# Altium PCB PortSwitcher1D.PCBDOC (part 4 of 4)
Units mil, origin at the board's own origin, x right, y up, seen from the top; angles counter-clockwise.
Board outline 6005.03 x 6005.03 mil, 4 copper layers (Top Layer, InternalPlane1, InternalPlane2, Bottom Layer); 153 components, 325 nets, 1175 pads, 173 vias.
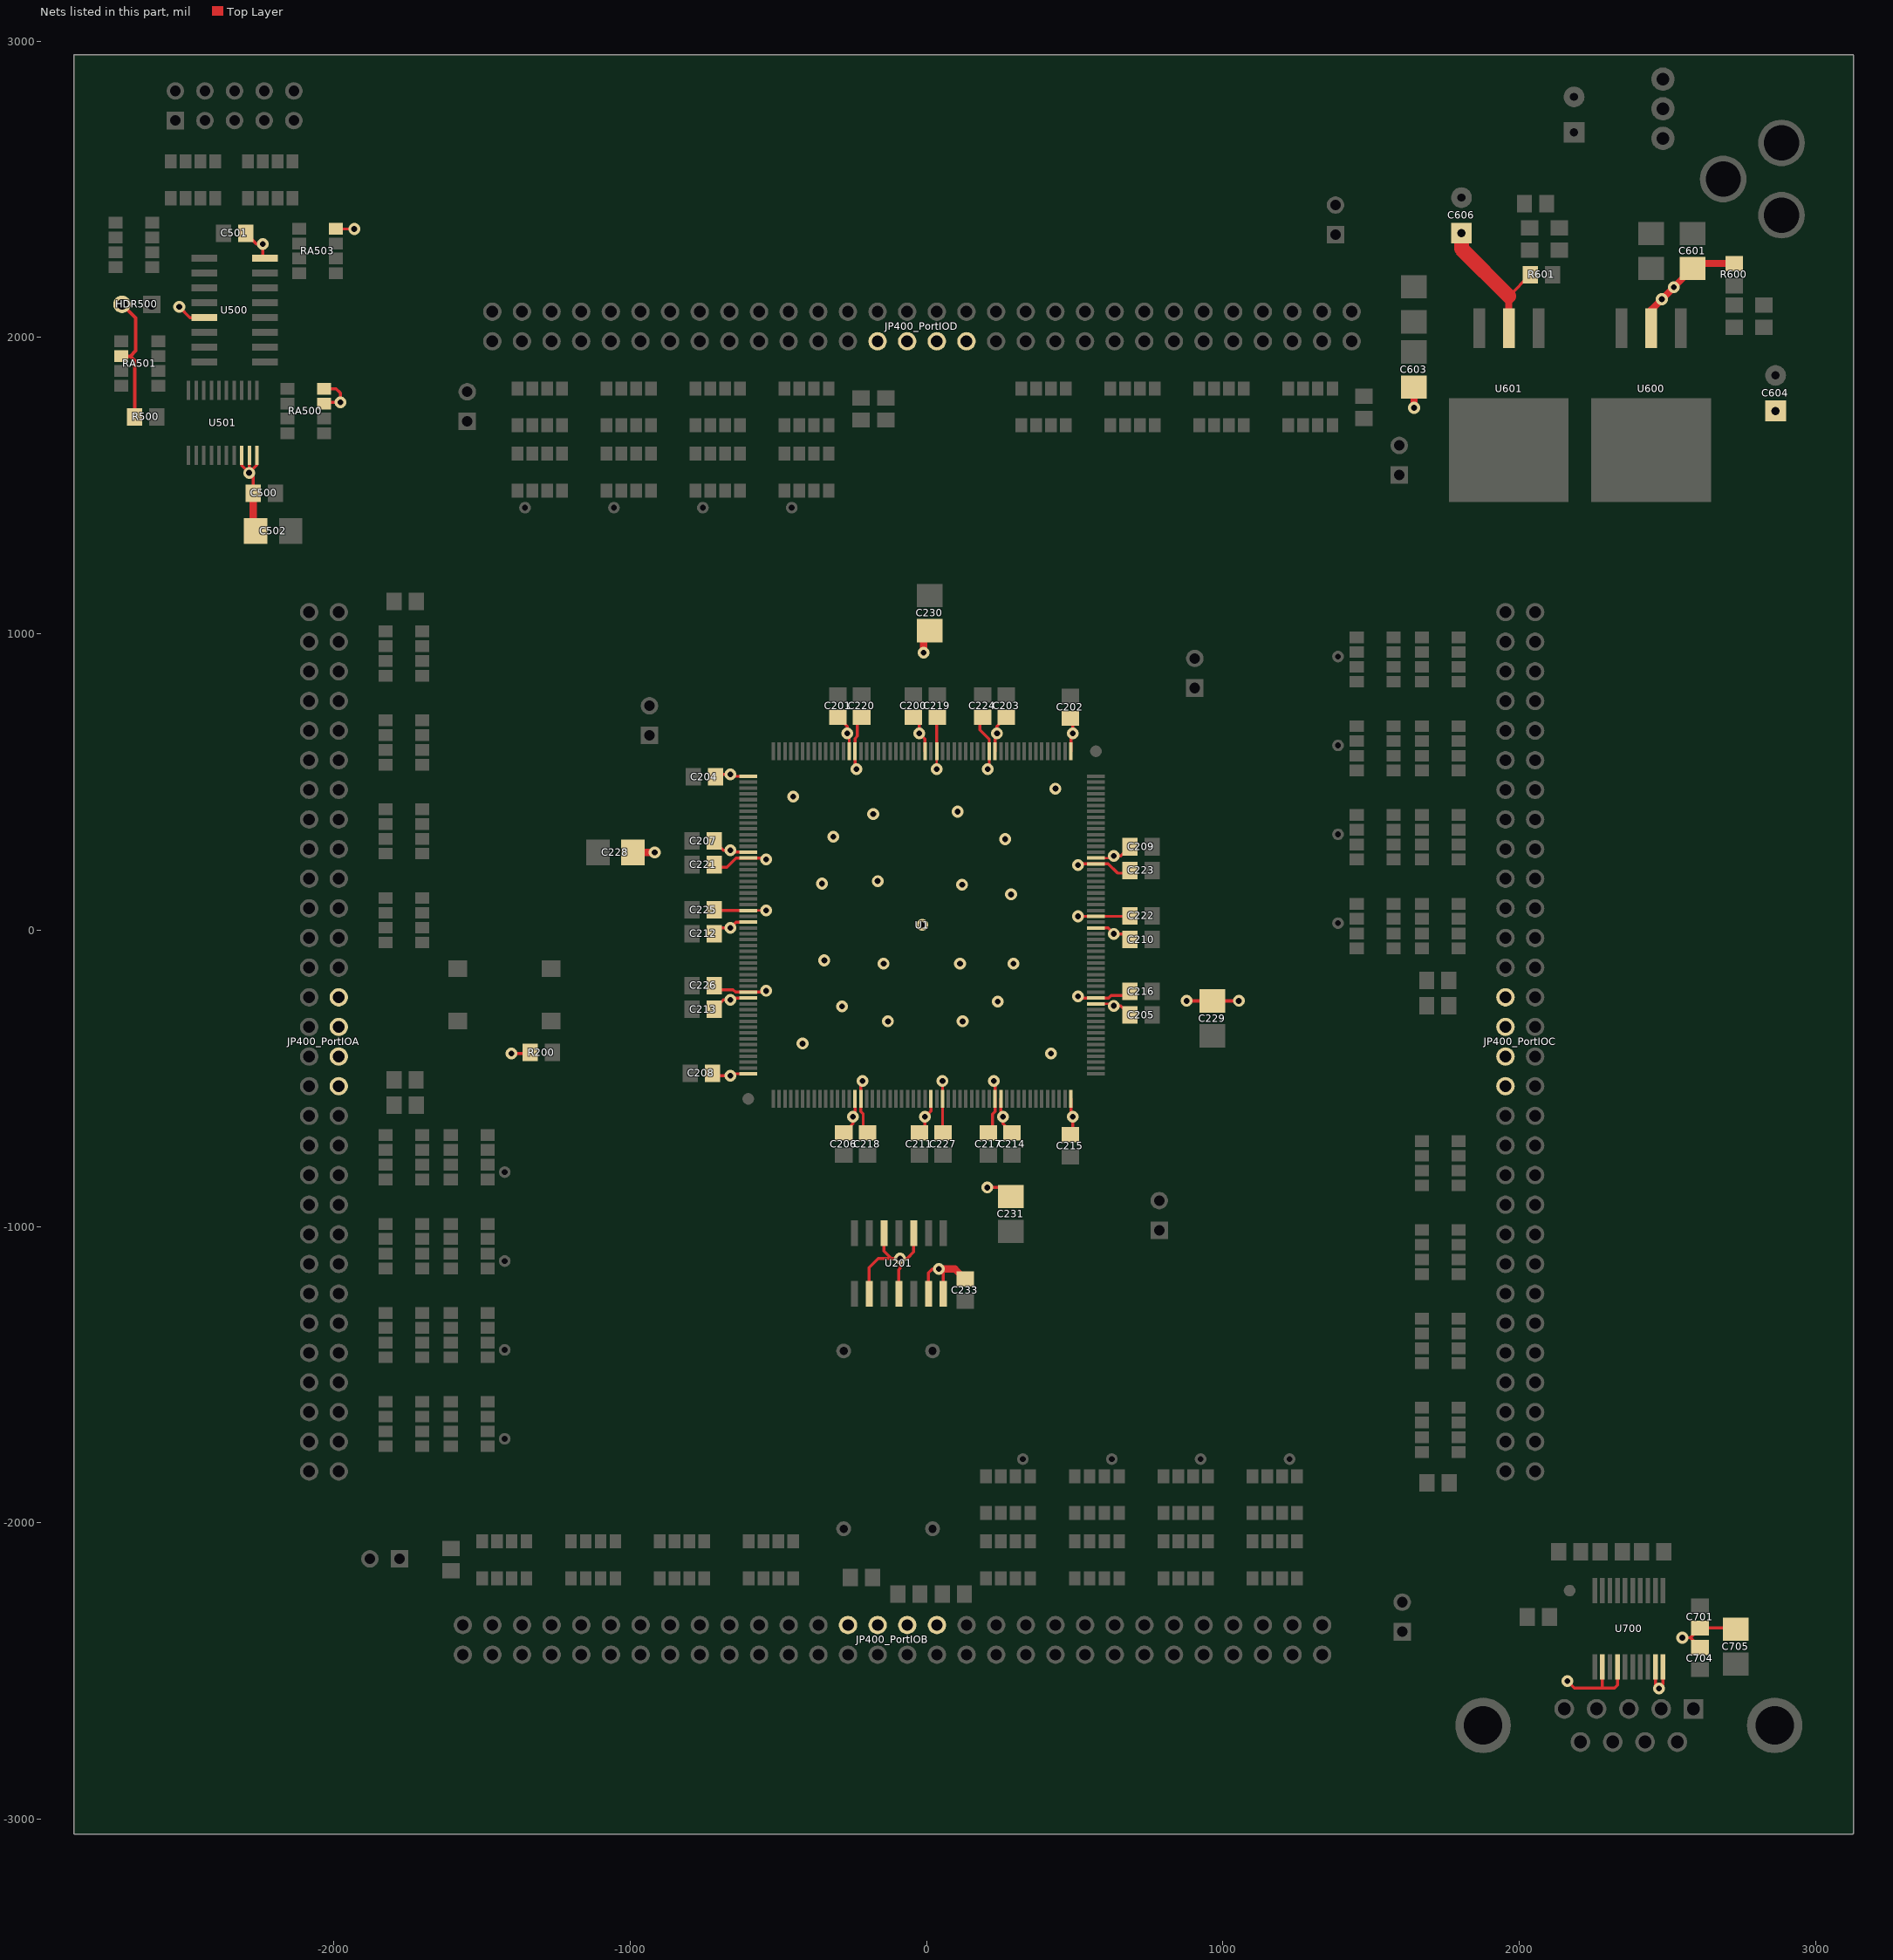
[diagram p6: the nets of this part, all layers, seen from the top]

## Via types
v1: diameter 40, hole 19.68, Top Layer to Bottom Layer, 173 vias

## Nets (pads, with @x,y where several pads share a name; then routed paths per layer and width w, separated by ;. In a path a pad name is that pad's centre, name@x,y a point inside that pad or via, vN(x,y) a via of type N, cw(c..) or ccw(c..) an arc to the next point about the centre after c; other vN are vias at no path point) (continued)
VCCINT: C216.1 C217.1 C218.1 C219.1 C220.1 C221.1 C222.2 C223.2 C224.2 C225.2 C226.2 C227.2 C230.1 C231.1 C603.1 C606.1 R601.2 U1.14 U1.28 U1.37 U1.67 U1.76 U1.90 U1.119 U1.128 U1.142 U1.172 U1.186 U1.195 U601.2 | length 4663.1
  Top Layer w8: U1.128@-601.88,66.5 v1(-541.37,66.5) U1.128@-601.88,66.5 ; v1(33.95,543.45) U1.76@33.95,603.91 v1(33.95,543.45) ; U1.186@53.63,-569.32 v1(53.63,-508.81) U1.186@53.63,-569.32 ; v1(510.84,46.82) U1.28@571.35,46.82 v1(510.84,46.82)
  Top Layer w10: C226.2@-717.86,-172.71 C226.2@-717.86,-177.12 ; C221.1@-712.86,212.29 -674.55,212.29 -643.17,243.67 ; C220.1@-205.26,719.89 C220.1@-209.67,719.89 ; C218.1@-185.58,-685.31 C218.1@-189.99,-685.31 ; C224.2@179.74,714.89 179.74,676.58 211.11,645.2 ; C217.1@194.42,-685.31 198.83,-685.31 C217.1@204.13,-680.01 ; v1(204.22,-868.54) 254.62,-868.53 C231.1@284.74,-898.65 ; C223.2@682.33,192.61 644.02,192.61 612.64,223.99 ; C216.1@687.33,-192.39 C216.1@687.33,-196.8 ; 1964.74,2139.69 R601.2@2037.33,2212.29 ; C226.2@-717.86,-177.12 C226.2@-712.57,-182.41 ; C226.2@-717.86,-177.12 C226.2@-712.57,-182.41 ; C226.2@-712.57,-182.41 C226.2@-693.89,-201.09 ; C226.2@-712.57,-182.41 C226.2@-693.89,-201.09 ; C225.2@-710.36,74.79 C225.2@-702.07,66.5 ; C225.2@-710.36,74.79 -717.86,82.29 C225.2@-710.36,74.79 ; C225.2@-710.36,74.79 C225.2@-702.07,66.5 ; C225.2@-702.07,66.5 U1.128@-601.88,66.5 C225.2@-702.07,66.5 ; C226.2@-693.89,-201.09 -652.88,-201.09 -644.89,-209.09 ; -644.89,-209.09 U1.142@-601.88,-209.09 ; -644.89,-209.09 U1.142@-601.88,-209.09 ; -643.17,243.67 U1.119@-601.88,243.67 ; -643.17,243.67 U1.119@-601.88,243.67 ; U1.142@-601.88,-209.09 v1@-545.8,-209.09 ; U1.142@-601.88,-209.09 v1@-545.8,-209.09 ; U1.119@-601.88,243.67 v1@-546.61,243.67 ; U1.119@-601.88,243.67 v1@-546.61,243.67 ; v1@-546.61,243.67 v1(-541.39,238.45) v1@-546.61,243.67 ; v1@-545.8,-209.09 v1(-541.39,-204.68) v1@-545.8,-209.09 ; v1@-241.64,547.83 v1(-237.23,543.42) v1@-241.64,547.83 ; v1@-241.64,547.83 U1.90@-241.64,603.91 ; v1@-241.64,547.83 U1.90@-241.64,603.91 ; U1.90@-241.64,603.91 -241.64,646.92 ; U1.90@-241.64,603.91 -241.64,646.92 ; -241.64,646.92 -233.65,654.91 C220.1@-233.65,695.91 ; C220.1@-233.65,695.91 C220.1@-214.97,714.59 ; C220.1@-233.65,695.91 C220.1@-214.97,714.6 ; -221.96,-612.34 -213.96,-620.33 -213.96,-661.33 -199.58,-675.72 C218.1@-195.28,-680.01 ; -221.96,-612.34 U1.172@-221.96,-569.32 ; -221.96,-612.34 U1.172@-221.96,-569.32 ; U1.172@-221.96,-569.32 v1@-221.96,-514.05 ; U1.172@-221.96,-569.32 v1@-221.96,-514.05 ; v1@-221.96,-514.05 v1(-216.74,-508.83) v1@-221.96,-514.05 ; C220.1@-214.97,714.59 C220.1@-209.67,719.89 ; C220.1@-214.97,714.6 C220.1@-209.67,719.89 ; C218.1@-195.28,-680.01 C218.1@-189.99,-685.31 ; C218.1@-195.28,-680.01 C218.1@-189.99,-685.31 ; C219.1@33.95,704.1 U1.76@33.95,603.91 C219.1@33.95,704.1 ; C219.1@33.95,704.1 C219.1@42.24,712.39 ; C219.1@33.95,704.1 C219.1@42.24,712.39 ; C219.1@42.24,712.39 49.74,719.89 C219.1@42.24,712.39 ; C227.2@53.63,-669.52 55.42,-671.31 C227.2@61.92,-677.81 ; C227.2@53.63,-669.52 U1.186@53.63,-569.32 C227.2@53.63,-669.52 ; C227.2@53.63,-669.52 C227.2@61.92,-677.81 ; C227.2@61.92,-677.81 69.42,-685.31 C227.2@61.92,-677.81 ; C217.1@204.13,-680.01 208.42,-675.72 C217.1@222.81,-661.33 ; C217.1@204.13,-680.01 C217.1@222.81,-661.33 ; v1@211.11,548.64 v1(205.89,543.42) v1@211.11,548.64 ; v1@211.11,548.64 U1.67@211.11,603.91 ; v1@211.11,548.64 U1.67@211.11,603.91 ; U1.67@211.11,603.91 211.11,645.2 ; U1.67@211.11,603.91 211.11,645.2 ; C217.1@222.81,-661.33 222.81,-620.33 230.8,-612.34 ; 230.8,-612.34 U1.195@230.8,-569.32 ; 230.8,-612.34 U1.195@230.8,-569.32 ; U1.195@230.8,-569.32 v1@230.8,-513.24 ; U1.195@230.8,-569.32 v1@230.8,-513.24 ; v1@230.8,-513.24 v1(226.39,-508.83) v1@230.8,-513.24 ; v1@515.27,223.98 v1(510.86,219.57) v1@515.27,223.98 ; v1@515.27,223.98 U1.37@571.35,223.98 ; v1@515.27,223.98 U1.37@571.35,223.98 ; v1@516.08,-228.77 v1(510.86,-223.55) v1@516.08,-228.77 ; v1@516.08,-228.77 U1.14@571.35,-228.77 ; v1@516.08,-228.77 U1.14@571.35,-228.77 ; U1.14@571.35,-228.77 614.36,-228.77 ; U1.14@571.35,-228.77 614.36,-228.77 ; U1.37@571.35,223.98 612.64,223.99 ; U1.37@571.35,223.98 612.64,223.99 ; 614.36,-228.77 622.36,-220.78 C216.1@663.36,-220.78 ; C216.1@663.36,-220.78 C216.1@682.04,-202.1 ; C216.1@663.36,-220.78 C216.1@682.04,-202.1 ; C216.1@682.04,-202.1 C216.1@687.33,-196.8 ; C216.1@682.04,-202.1 C216.1@687.33,-196.8 ; U1.28@571.35,46.82 671.55,46.82 U1.28@571.35,46.82
  Top Layer w24: v1(-10.34,936.35) -10.34,1013.16 C230.1@-10.26,1013.24 ; v1(1644.74,1762.91) C603.1@1644.74,1833.24 ; U601.2@1964.74,2032.29 1964.74,2139.69
  Top Layer w50: C606.1@1804.74,2352.29 1804.74,2299.69 1964.74,2139.69
  other v1: 419.74,-415.67 -418.7,-382.71 -130.39,-307.71 121.51,-307.71 -285.26,-257.24 239.74,-240.52 -145.15,-112.71 112.66,-112.71 292.73,-112.71 -345.26,-101.77 -15.26,18.28 284.74,120.61 119.74,153.08 -352.78,157.29 -165.26,165.88 265.18,307.29 -315.26,315.44 -180.26,392.2 104.74,400.07 -450.26,451.24 434.74,477.8
VCCO: C200.1 C201.1 C202.1 C203.1 C204.1 C205.1 C206.1 C207.1 C208.2 C209.2 C210.2 C211.2 C212.2 C213.2 C214.2 C215.2 C228.1 C229.1 C233.1 C500.1 C501.1 C502.1 C601.1 C604.1 C701.1 C704.1 C705.1 HDR500.2 JP400_PortIOA.28 JP400_PortIOA.30 JP400_PortIOA.32 JP400_PortIOA.34 JP400_PortIOB.28 JP400_PortIOB.30 JP400_PortIOB.32 JP400_PortIOB.34 JP400_PortIOC.28 JP400_PortIOC.30 JP400_PortIOC.32 JP400_PortIOC.34 JP400_PortIOD.28 JP400_PortIOD.30 JP400_PortIOD.32 JP400_PortIOD.34 pad.0 R200.2 R500.1 R600.2 RA500.7 RA500.8 RA501.6 RA503.8 U1.13 U1.26 U1.38 U1.53 U1.66 U1.78 U1.91 U1.105 U1.118 U1.130 U1.143 U1.156 U1.171 U1.184 U1.196 U1.208 U201.3 U201.5 U201.9 U201.11 U201.13 U201.14 U500.5 U500.16 U501.18 U501.19 U501.20 U600.2 U700.12 U700.14 U700.19 U700.20 | length 7901
  Top Layer w8: v1@-254.28,-632.31 -250.07,-628.1 v1@-244.28,-622.31 ; -241.64,-604.68 U1.171@-241.64,-569.32 ; v1@253.12,-622.31 v1@258.91,-628.1 ; v1@-660.65,-237.19 -661.17,-237.71 -662.39,-238.93 -664.22,-240.76 -664.87,-241.41 v1@-660.65,-237.19 ; v1@-660.65,-237.19 -654.87,-231.41 v1@-660.65,-237.19 ; v1@-269.75,662.68 -263.97,656.9 v1@-269.75,662.68 ; v1@-269.75,662.68 -273.97,666.9 v1@-269.75,662.68 ; v1@258.91,-628.1 263.12,-632.31 v1@258.91,-628.1 ; v1@625.18,-248.46 U1.13@571.35,-248.46 v1@625.18,-248.46 ; v1@625.18,-248.46 631.86,-248.46 v1@625.18,-248.46 ; v1@625.18,243.67 U1.38@571.35,243.67 v1@625.18,243.67 ; v1@625.18,243.67 631.86,243.67 v1@625.18,243.67 ; v1@630.12,-256.88 634.34,-261.09 v1@630.12,-256.88 ; v1@630.12,-256.88 626.74,-253.49 624.34,-251.09 v1@630.12,-256.88 ; -637.23,-228.77 U1.143@-601.88,-228.77 -637.23,-228.77 ; U1.91@-261.33,603.91 -261.33,639.26 U1.91@-261.33,603.91
  Top Layer w10: v1(-2521.99,2103.79) -2485.49,2067.29 U500.5@-2437.63,2067.29 ; U501.18@-2311.29,1603.04 -2311.29,1568.43 v1(-2286.34,1543.48) ; C501.1@-2297.86,2352.29 -2261.49,2315.92 v1(-2240.09,2315.92) -2240.09,2274.48 U500.16@-2232.9,2267.29 ; U501.19@-2285.7,1603.04 v1@-2285.7,1544.11 ; C500.1@-2272.67,1475.08 -2272.67,1529.81 v1(-2286.34,1543.48) ; U501.20@-2260.11,1603.04 -2260.11,1569.71 v1@-2285.7,1544.11 ; RA500.8@-2033.26,1827.29 -1992.54,1827.29 -1978.34,1813.09 v1(-1978.34,1781.6) RA500.7@-2028.95,1781.6 ; RA503.8@-1992.49,2366.52 v1(-1931.59,2366.52) ; v1(-1401.22,-416.23) -1341.19,-416.23 R200.2@-1337.67,-412.71 ; C206.1@-279.58,-684.31 -248.33,-653.05 v1(-248.33,-629.83) -241.64,-623.15 U1.171@-241.64,-569.32 ; U201.9@-194,-1226.8 -194,-1138.56 -162.86,-1107.42 -65.45,-1107.42 -44,-1085.98 U201.3@-44,-1022.08 ; U201.5@-144,-1022.08 -144,-1082.98 -119.57,-1107.42 ; U201.11@-94,-1226.8 -94,-1145.82 -90.05,-1141.86 pad.0@-90.05,-1107.42 ; U201.13@6,-1226.8 6,-1157.01 19.86,-1143.14 v1(40.84,-1143.14) 56,-1158.3 U201.14@56,-1226.8 ; v1(2161.85,-2533.8) 2185.46,-2557.42 2321.26,-2557.42 2331.35,-2547.32 U700.14@2331.35,-2486.65 ; 2280.17,-2557.18 U700.12@2280.17,-2486.65 ; U700.19@2459.3,-2486.65 2459.3,-2546.82 v1(2471.3,-2558.82) 2484.89,-2545.23 U700.20@2484.89,-2486.65 ; v1(2550.02,-2387.6) 2577.24,-2387.6 C701.1@2609.74,-2355.11 2726.19,-2355.11 C705.1@2729.74,-2358.65 ; 2577.03,-2387.6 C704.1@2609.74,-2420.31 ; v1(-2286.34,1543.48) v1@-2285.7,1544.11 ; C204.1@-717.86,522.29 -722.86,517.29 C204.1@-717.86,522.29 ; C204.1@-717.86,522.29 C204.1@-714.21,525.94 ; C204.1@-717.86,522.29 C204.1@-714.21,525.94 ; C208.2@-714.21,-491.36 C208.2@-722.86,-482.71 C208.2@-714.21,-491.36 ; C208.2@-714.21,-491.36 -669.92,-491.36 v1(-662.39,-491.36) ; C208.2@-714.21,-491.36 v1(-662.39,-491.36) ; C204.1@-714.21,525.94 C204.1@-712.86,525.94 ; C204.1@-714.21,525.94 C204.1@-712.86,525.94 ; C204.1@-712.86,525.94 -666.61,525.94 v1(-662.39,525.94) ; C204.1@-712.86,525.94 v1(-662.39,525.94) ; C212.2@-697.7,7.45 -706.06,-0.91 C212.2@-716.86,-11.71 C212.2@-697.7,7.45 ; C212.2@-697.7,7.45 -688.11,7.45 v1(-662.39,7.45) ; C212.2@-697.7,7.45 v1(-662.39,7.45) ; -685.61,-235.46 C213.2@-716.86,-266.71 -685.61,-235.46 ; -685.61,-235.46 -667.26,-235.46 v1(-662.39,-235.46) ; -685.61,-235.46 v1(-662.39,-235.46) ; -685.61,270.04 -673.26,270.04 -664.01,270.04 v1(-662.39,270.04) ; -685.61,270.04 C207.1@-716.86,301.29 -685.61,270.04 ; -685.61,270.04 v1(-662.39,270.04) ; v1(-662.39,-491.36) v1@-655.71,-484.68 ; v1(-662.39,-491.36) v1@-655.71,-484.68 ; v1(-662.39,-235.46) v1@-655.71,-228.77 ; v1(-662.39,-235.46) v1@-655.71,-228.77 ; v1(-662.39,7.45) -642.71,27.13 ; v1(-662.39,7.45) -642.71,27.13 ; v1(-662.39,270.04) v1@-655.71,263.35 ; v1(-662.39,270.04) v1@-655.71,263.35 ; v1(-662.39,525.94) v1@-655.71,519.26 ; v1(-662.39,525.94) v1@-655.71,519.26 ; v1@-655.71,-484.68 U1.156@-601.88,-484.68 v1@-655.71,-484.68 ; v1@-655.71,-228.77 U1.143@-601.88,-228.77 v1@-655.71,-228.77 ; v1@-655.71,263.35 U1.118@-601.88,263.35 v1@-655.71,263.35 ; v1@-655.71,519.26 U1.105@-601.88,519.26 v1@-655.71,519.26 ; -642.71,27.13 U1.130@-601.88,27.13 -642.71,27.13 ; v1(-268.01,664.42) v1@-261.33,657.73 ; v1(-268.01,664.42) -268.01,687.64 ; v1(-268.01,664.42) -268.01,687.64 ; v1(-268.01,664.42) v1@-261.33,657.73 ; -268.01,687.64 C201.1@-299.26,718.89 -268.01,687.64 ; v1@-261.33,657.73 U1.91@-261.33,603.91 v1@-261.33,657.73 ; v1(-25.11,664.42) -5.42,644.73 ; v1(-25.11,664.42) -25.11,666.98 C200.1@-25.11,699.73 ; v1(-25.11,664.42) C200.1@-25.11,699.73 ; v1(-25.11,664.42) -5.42,644.73 ; C200.1@-25.11,699.73 C200.1@-44.26,718.89 C200.1@-25.11,699.73 ; C211.2@-5.42,-665.15 -6.62,-666.35 C211.2@-24.58,-684.31 C211.2@-5.42,-665.15 ; C211.2@-5.42,-665.15 -5.42,-653.71 -5.42,-639.86 v1(-5.42,-629.83) ; C211.2@-5.42,-665.15 v1(-5.42,-629.83) ; v1(-5.42,-629.83) 14.26,-610.15 ; v1(-5.42,-629.83) 14.26,-610.15 ; -5.42,644.73 U1.78@-5.42,603.91 -5.42,644.73 ; 14.26,-610.15 U1.184@14.26,-569.32 14.26,-610.15 ; v1@230.8,657.73 U1.66@230.8,603.91 v1@230.8,657.73 ; v1@230.8,657.73 v1(237.48,664.42) ; v1@230.8,657.73 v1(237.48,664.42) ; v1(237.48,664.42) 237.48,666.04 237.48,675.29 237.48,687.64 ; v1(237.48,664.42) 237.48,687.64 ; 237.48,687.64 C203.1@268.74,718.89 237.48,687.64 ; v1@250.49,-623.15 v1(257.17,-629.83) ; v1@250.49,-623.15 U1.196@250.48,-569.32 v1@250.49,-623.15 ; v1@250.49,-623.15 v1(257.17,-629.83) ; 257.17,-653.05 260.17,-656.06 C214.2@288.42,-684.31 257.17,-653.05 ; 257.17,-653.05 257.17,-642.71 257.17,-634.14 v1(257.17,-629.83) ; 257.17,-653.05 v1(257.17,-629.83) ; v1@486.7,-623.15 486.7,-600.68 U1.208@486.7,-569.32 v1@486.7,-623.15 ; v1@486.7,-623.15 v1(493.39,-629.83) ; v1@486.7,-623.15 v1(493.39,-629.83) ; v1@486.7,657.73 486.7,641.32 U1.53@486.7,603.91 v1@486.7,657.73 ; v1@486.7,657.73 v1(493.39,664.42) ; v1@486.7,657.73 v1(493.39,664.42) ; C202.1@489.74,719.89 C202.1@493.39,716.24 ; C202.1@489.74,719.89 484.74,724.89 C202.1@489.74,719.89 ; C202.1@489.74,719.89 C202.1@493.39,716.24 ; C215.2@493.39,-681.65 C215.2@484.74,-690.31 C215.2@493.39,-681.65 ; C215.2@493.39,-681.65 v1(493.39,-629.83) ; C215.2@493.39,-681.65 v1(493.39,-629.83) ; v1(493.39,664.42) C202.1@493.39,714.89 ; v1(493.39,664.42) C202.1@493.39,714.89 ; C202.1@493.39,714.89 C202.1@493.39,716.24 ; C202.1@493.39,714.89 C202.1@493.39,716.24 ; 612.18,7.45 U1.26@571.35,7.45 612.18,7.45 ; 612.18,7.45 v1(631.86,-12.23) ; 612.18,7.45 v1(631.86,-12.23) ; v1(631.86,-255.14) 625.18,-248.46 v1(631.86,-255.14) ; v1(631.86,-255.14) 636.74,-255.14 655.08,-255.14 ; v1(631.86,-255.14) 655.08,-255.14 ; v1(631.86,-12.23) C210.2@667.18,-12.23 ; v1(631.86,-12.23) C210.2@667.18,-12.23 ; v1(631.86,250.35) 625.18,243.67 v1(631.86,250.35) ; v1(631.86,250.35) 655.08,250.35 ; v1(631.86,250.35) 655.08,250.35 ; 655.08,-255.14 C205.1@686.33,-286.39 655.08,-255.14 ; 655.08,250.35 C209.2@686.33,281.61 655.08,250.35 ; C210.2@667.18,-12.23 C210.2@686.33,-31.39 C210.2@667.18,-12.23
  Top Layer w12: RA501.6@-2717.26,1937.29 -2687.51,1937.29 ; HDR500.2@-2715.26,2112.29 -2668.61,2065.63 -2668.61,1956.19 -2687.51,1937.29 ; R500.1@-2672.67,1732.29 -2672.67,1922.45 -2687.51,1937.29 ; v1(877.03,-238.55) v1(1053.36,-238.55)
  Top Layer w24: C500.1@-2272.67,1475.08 -2272.67,1355.64 C502.1@-2264.32,1347.29 ; C228.1@-991.21,262.29 v1(-917.59,262.31) ; v1(40.84,-1143.14) 95.54,-1143.14 C233.1@130,-1177.6 ; U600.2@2444.74,2032.29 2444.74,2093.24 C601.1@2584.74,2233.24 2601.19,2249.69 R600.2@2724.74,2249.69
  other v1: 2480.94,2129.45 2521.08,2169.58
pads on no net: J700.9 RA500.3 RA500.4 RA500.5 RA500.6 RA502.1 RA502.8 RA503.4 RA503.5 U200.1 U201.4 U201.6 U201.8 U201.10 U201.12 U501.2 U501.9 U501.12 U501.13 U501.14 U501.15 U501.16 U600.4 U601.4 U700.1 U700.10 U700.11

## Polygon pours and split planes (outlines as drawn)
VCCINT on Top Layer "Top Layer-VCCINT" (solid, remove dead copper, pour order 1000): -637.15,622.45 -639.12,-560.32 583.01,-562.71 584.98,56.65 588.91,622.29
VCCINT on Bottom Layer "Bottom Layer-VCCINT" (solid, remove dead copper, pour order 1001): -1321.03,1118.39 -1321.03,-1654.52 1567.99,-1654.52 1567.99,987.52 1830.72,1250.24 2210.54,1630.07 2210.54,2421.2 1966.51,2665.24 1648.68,2665.24 1516.82,2533.38 1516.82,1851.47 1181.28,1515.92 -0.5,1515.92 -395.09,1121.34 -1321.03,1121.34
GND on InternalPlane1 (split plane): 3087.8,-3010.77 -2838.33,-3010.77 -2838.33,2915.35 3087.8,2915.35
VCCO on InternalPlane2 (split plane): 3087.8,-3010.77 -2838.33,-3010.77 -2838.33,2915.35 3087.8,2915.35

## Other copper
Top Layer:
  text "1" at -2328.07,-2734.45 h60
Bottom Layer:
  text "4" at -2123.07,-2734.45 h60
InternalPlane1 (plane layer: these items are gaps in the copper):
  rectangle: -2353.07,-2744.45 -2288.07,-2664.45
  rectangle: -2213.07,-2744.45 -2063.07,-2664.45
  text "2" at -2273.07,-2734.45 h60
InternalPlane2 (plane layer: these items are gaps in the copper):
  rectangle: -2353.07,-2744.45 -2213.07,-2664.45
  rectangle: -2138.07,-2744.45 -2063.07,-2664.45
  text "3" at -2193.07,-2734.45 h60

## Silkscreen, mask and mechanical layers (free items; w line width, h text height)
Top Overlay:
  text "Programming/Debug" at -1947.34,2763.07 h60
  text "Port D" at -232.73,2158.35 h60
  text "15" at -807.26,2140.85 h45
  text "5" at -1283.51,2138.88 h45
  text "55" at 1195.18,2138.88 h45
  text "35" at 193.47,2136.91 h45
  text "45" at 694.33,2136.91 h45
  text "10" at -1034.56,1947.99 h45 r180
  text "20" at -523.87,1940.11 h45 r180
  text "30" at -30.88,1939.13 h45 r180
  text "40" at 473.91,1939.13 h45 r180
  text "50" at 970.83,1939.13 h45 r180
  text "5" at 2104.75,891.45 h45 r270
  text "55" at -2135.28,834.43 h45 r90
  text "10" at 1913.85,642.5 h45 r90
  text "50" at -1935.53,610.08 h45 r270
  text "15" at 2106.72,415.19 h45 r270
  text "45" at -2133.31,333.58 h45 r90
  text "20" at 1905.98,131.8 h45 r90
  text "40" at -1935.53,113.16 h45 r270
  text "Rev 1.1" at -2738.47,5.91 h45 r90
  text "Port C" at 2124.22,-159.33 h60 r270
  text "35" at -2133.31,-167.28 h45 r90
  text "Reset" at -1236.89,-239.11 h60
  text "30" at 1905,-361.18 h45 r90
  text "30" at -1935.53,-391.63 h45 r270
  text "35" at 2102.78,-585.54 h45 r270
  text "Port A" at -2154.75,-593.48 h60 r90
  text "40" at 1905,-865.98 h45 r90
  text "20" at -1936.51,-884.62 h45 r270
  text "EL 2003-2004 Altium Ltd" at -2664.67,-926.93 h45 r90
  text "PortSwitcher" at -2745.36,-930.86 h45 r90
  text "45" at 2102.78,-1086.39 h45 r270
  text "15" at -2137.25,-1168.01 h45 r90
  text "50" at 1905,-1362.9 h45 r90
  text "10" at -1944.38,-1395.31 h45 r270
  text "55" at 2104.75,-1587.25 h45 r270
  text "5" at -2135.28,-1644.26 h45 r90
  text "50" at -1101.75,-2296.67 h45
  text "40" at -604.83,-2296.67 h45
  text "30" at -100.04,-2296.67 h45
  text "20" at 392.94,-2297.66 h45
  text "10" at 903.64,-2305.53 h45
  text "45" at -825.25,-2494.46 h45 r180
  text "35" at -324.39,-2494.46 h45 r180
  text "55" at -1326.11,-2496.42 h45 r180
  text "5" at 1152.59,-2496.42 h45 r180
  text "15" at 676.33,-2498.39 h45 r180
  text "Port B" at 101.81,-2515.9 h60 r180
Bottom Overlay:
  text "Port D" at 100.97,2149.71 h60
  text "PORT A" at -2146.1,-259.78 h60 r90
  text "Port C" at 2115.57,-493.04 h60 r270
  text "Port B" at -231.9,-2507.25 h60 r180
Board Outline:
  lines w5: -2875.26,-3047.71 3124.74,-3047.71 3124.74,2952.29 -2875.26,2952.29 -2875.26,-3047.71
